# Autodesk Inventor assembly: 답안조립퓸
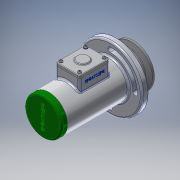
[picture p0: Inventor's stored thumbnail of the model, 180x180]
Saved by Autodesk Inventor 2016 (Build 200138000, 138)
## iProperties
Created: 2017-05
Part Number: 답안조립퓸
Material: 일반
Document SubType Name: Assembly
Designer: USER
Author: USER
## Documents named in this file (20)
- C:\Users\USER\Desktop\470508V1020\답안조립퓸.iam
- C:\Users\USER\Desktop\470508V1020\본체1.ipt
- C:\Users\USER\Desktop\470508V1020\V-벨트풀리.ipt
- C:\Users\USER\Desktop\470508V1020\너트 M10.ipt
- C:\Users\USER\Desktop\470508V1020\멈춤링 15 x 1.ipt
- C:\Users\USER\Desktop\470508V1020\멈춤링 35x1.6.ipt
- C:\Users\USER\Desktop\470508V1020\베어링 15 x 35 x 11.ipt
- C:\Users\USER\Desktop\470508V1020\볼트 M4 x 10.ipt
- C:\Users\USER\Desktop\470508V1020\부시1.ipt
- C:\Users\USER\Desktop\470508V1020\부시2.ipt
- C:\Users\USER\Desktop\470508V1020\사이드 커버.ipt
- 사이드 커버.ipt
- C:\Users\USER\Desktop\470508V1020\십자볼트 M3 x 10.ipt
- C:\Users\USER\Desktop\470508V1020\오일 실 15 25 7.ipt
- C:\Users\USER\Desktop\470508V1020\와셔 3x6.ipt
- C:\Users\USER\Desktop\470508V1020\와셔 4x16.ipt
- C:\Users\USER\Desktop\470508V1020\와셔 10x21.ipt
- C:\Users\USER\Desktop\470508V1020\축.ipt
- C:\Users\USER\Desktop\470508V1020\키 4 x 4 x 18.ipt
- C:\Users\USER\Desktop\470508V1020\탑 커버.ipt
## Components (2 placed, 2 different names)
1. V-벨트풀리:1
2. ISO 4017 M4 x 10:1
